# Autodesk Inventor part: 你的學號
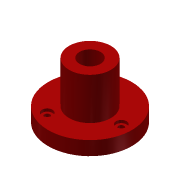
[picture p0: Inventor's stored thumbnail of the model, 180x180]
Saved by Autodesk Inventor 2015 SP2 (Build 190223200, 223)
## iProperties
Created: 2019-07
Part Number: 你的學號
Material: 一般
Document SubType Name: Modeling
Density: 1 g/cm^3
Appearance: 平滑 - 紅色
Author: 你的姓名
Title: 轉正剖面視圖
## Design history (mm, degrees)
sketch "草圖5"
  geometry: L1 (0, 0)-(0, 66.981); L2 (-15, 80)-(-30, 80); L3 (-30, 80)-(-30, 20); L4 (-30, 20)-(-60, 20); L5 (-60, 20)-(-60, 0); L6 (-60, 0)-(-15, 0); L7 (-15, 0)-(-15, 80)
  constraints: 14 end point, 4 perpendicular, 2 vertical, 1 horizontal, 1 horizontal alignment
  dimensions: "d18" = 30 diameter of L7 L1; "d19" = 80 distance of L6.end L2.start; "d20" = 60 diameter of L3 L1; "d21" = 20 distance of L4.end L5.end; "d22" = 120 diameter of L5 L1
revolve "迴轉1" sketch "草圖5" stored, may be unused: angle "d23" = 90 deg
sketch "草圖6"
  geometry: L1 (0, 0)-(45, 0); C1 r 60 at (0, 0) reference; C2 r 30 at (0, 0) reference; C3 r 7.5 at (45, 0); 1 further point
  constraints: 2 end point, 1 centre point, 1 coincident, 1 horizontal
  dimensions: "d24" = 45 distance of L1.start L1.end; "d25" = 15 diameter of C3
extrude "擠出5" cut sketch "草圖6" distance "d26" = 4; taper "d27" = 0 deg
sketch "草圖7"
  geometry: C1 r 7.5 at (0, 0) reference; C2 r 4 at (0, 0); 1 further point
  constraints: 1 centre point, 1 coincident
  dimensions: "d28" = 8 diameter of C2
extrude "擠出6" cut sketch "草圖7" stored distance "d29" = 4; taper "d30" = 0 deg
pattern_circular "環形陣列1" dims angle "d32" = 360 deg
node "實體2"
node "投影迴路2"
